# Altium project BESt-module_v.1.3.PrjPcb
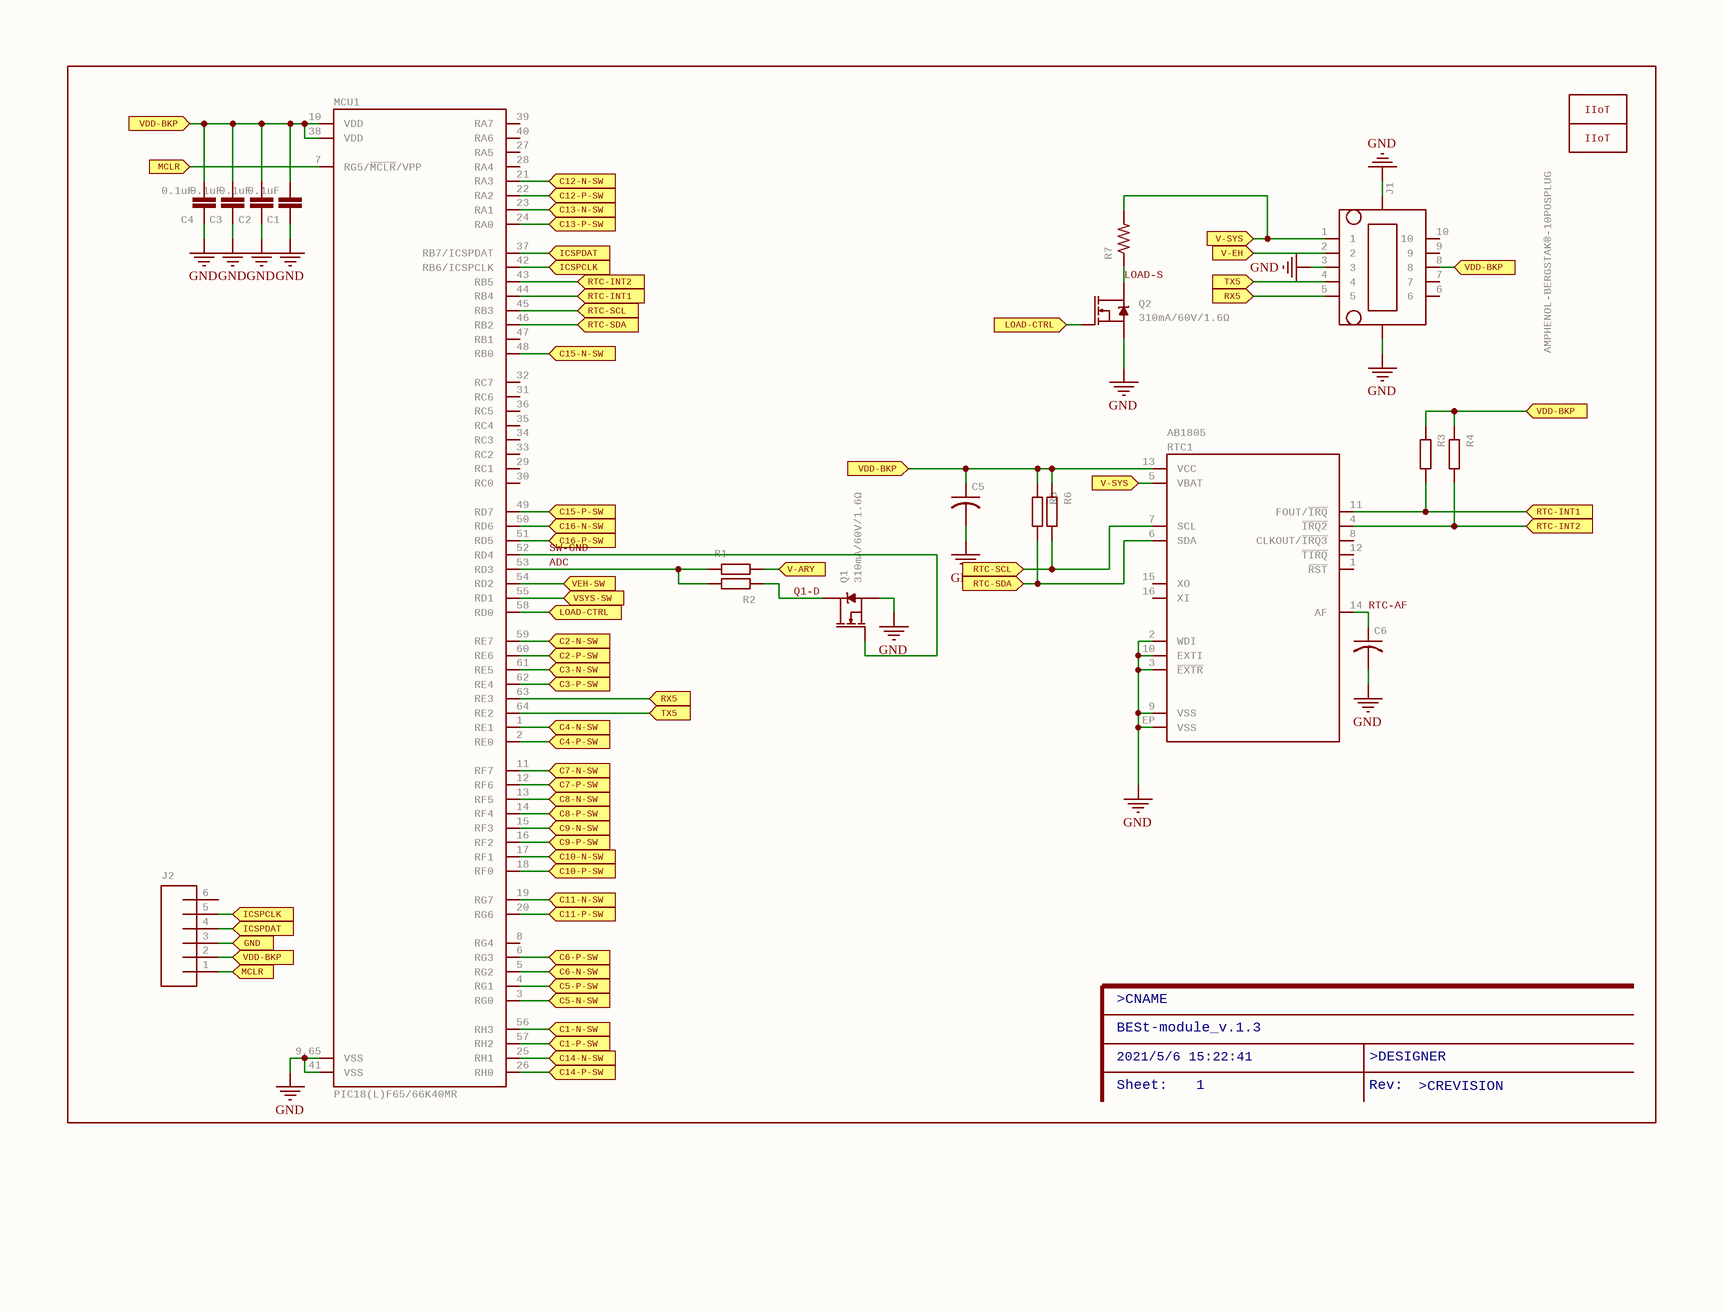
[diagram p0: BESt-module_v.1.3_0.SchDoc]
2 sheets, 61 parts. Net scope: flat (ports and power ports of the same name join across sheets).
Board file: BESt-module_v.1.3.PcbDoc
Sheets:
  BESt-module_v.1.3_0.SchDoc
  BESt-module_v.1.3_1.SchDoc

## Sheet BESt-module_v.1.3_0.SchDoc: BESt-module_v.1.3
size 302 x 229 mm; Origin: Eagle; Date: 2021/5/6 15:22:41; SheetNumber: 1; GateName_1: G$1; SymbolName_1: FR-A4L; LibraryName: SparkFun-Aesthetics; DeviceSetName: FRAME-A4L; Sheet: Sheet:; CNAME: >CNAME; Rev: Rev:; DESIGNER: >DESIGNER; CREVISION: >CREVISION

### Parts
C1  0.1uF  [0603]
C2  0.1uF  [0603]
C3  0.1uF  [0603]
C4  0.1uF  [0603]
C5  C-USC0402  [C0402]  (value not drawn)
C6  C-USC0402  [C0402]  (value not drawn)
J1  AMPHENOL-BERGSTAK®-10POSPLUG  [10132797-10POS-PLUG]
J2  CONN_06NO_SILK_NO_POP  [1X06_NO_SILK]  (value not drawn)
LOGO1  IIOT  [IIOT]
LOGO2  IIOT  [IIOT]
MCU1  PIC18(L)F65/66K40MR  [QFN50P900X900X100-65T715N]
Q1  310mA/60V/1.6Ω  [SOT323]
Q2  310mA/60V/1.6Ω  [SOT323]
R1  R-EU_R0402  [R0402]  (value not drawn)
R2  R-EU_R0402  [R0402]  (value not drawn)
R3  R-EU_R0402  [R0402]  (value not drawn)
R4  R-EU_R0402  [R0402]  (value not drawn)
R5  R-EU_R0402  [R0402]  (value not drawn)
R6  R-EU_R0402  [R0402]  (value not drawn)
R7  R-US_R0805  [R0805]  (value not drawn)
RTC1  AB1805  [QFN-16-3X3]

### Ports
C1-N-SW (in), C1-P-SW (in), C2-N-SW (in), C2-P-SW (in), C3-N-SW (in), C3-P-SW (in), C4-N-SW (in), C4-P-SW (in), C5-N-SW (in), C5-P-SW (in), C6-N-SW (in), C6-P-SW (in), C7-N-SW (in), C7-P-SW (in), C8-N-SW (in), C8-P-SW (in), C9-N-SW (in), C9-P-SW (in), C10-N-SW (in), C10-P-SW (in), C11-N-SW (in), C11-P-SW (in), C12-N-SW (in), C12-P-SW (in), C13-N-SW (in), C13-P-SW (in), C14-N-SW (in), C14-P-SW (in), C15-N-SW (in), C15-P-SW (in), C16-N-SW (in), C16-P-SW (in), GND (in), ICSPCLK (in), ICSPDAT (in), LOAD-CTRL (in), MCLR (in), RTC-INT1 (in), RTC-INT2 (in), RTC-SCL (in), RTC-SDA (in), RX5 (in), TX5 (in), V-ARY (in), V-EH (in), V-SYS (in), VDD-BKP (in), VEH-SW (in), VSYS-SW (in)

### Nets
GND: C1.1 C2.1 C3.1 C4.1 C5.2 C6.2 J1.3 J1.MNT1 J1.MNT2 MCU1.9,65(VSS) MCU1.41(VSS) Q1.2(S) Q2.2(S) RTC1.2(WDI) RTC1.3(~{EXTR}) RTC1.9(VSS) RTC1.10(EXTI) RTC1.EP(VSS)
ADC: MCU1.53(RD3) R1.1 R2.2
C9-N: MCU1.16(RF2) ; port C9-P-SW
LOAD-S: Q2.3(D) R7.1
Q1-D: Q1.3(D) R2.1
RTC-AF: C6.1 RTC1.14(AF)
SW-GND: MCU1.52(RD4) Q1.1(G)
NetC1_2: C1.2 C2.2 C3.2 C4.2 C5.1 J1.8 J2.2 MCU1.10(VDD) MCU1.38(VDD) R3.1 R4.1 R5.1 R6.1 RTC1.13(VCC) ; port VDD-BKP
NetJ1_1: J1.1 R7.2 RTC1.5(VBAT) ; port V-SYS
NetJ1_2: J1.2 ; port V-EH
NetJ1_4: J1.4 MCU1.64(RE2) ; port TX5
NetJ1_5: J1.5 MCU1.63(RE3) ; port RX5
NetJ2_1: J2.1 MCU1.7(RG5/~{MCLR}/VPP) ; port MCLR
NetJ2_3: J2.3 ; port GND
NetJ2_4: J2.4 MCU1.37(RB7/ICSPDAT) ; port ICSPDAT
NetJ2_5: J2.5 MCU1.42(RB6/ICSPCLK) ; port ICSPCLK
NetMCU1_1: MCU1.1(RE1) ; port C4-N-SW
NetMCU1_2: MCU1.2(RE0) ; port C4-P-SW
NetMCU1_3: MCU1.3(RG0) ; port C5-N-SW
NetMCU1_4: MCU1.4(RG1) ; port C5-P-SW
NetMCU1_5: MCU1.5(RG2) ; port C6-N-SW
NetMCU1_6: MCU1.6(RG3) ; port C6-P-SW
NetMCU1_11: MCU1.11(RF7) ; port C7-N-SW
NetMCU1_12: MCU1.12(RF6) ; port C7-P-SW
NetMCU1_13: MCU1.13(RF5) ; port C8-N-SW
NetMCU1_14: MCU1.14(RF4) ; port C8-P-SW
NetMCU1_15: MCU1.15(RF3) ; port C9-N-SW
NetMCU1_17: MCU1.17(RF1) ; port C10-N-SW
NetMCU1_18: MCU1.18(RF0) ; port C10-P-SW
NetMCU1_19: MCU1.19(RG7) ; port C11-N-SW
NetMCU1_20: MCU1.20(RG6) ; port C11-P-SW
NetMCU1_21: MCU1.21(RA3) ; port C12-N-SW
NetMCU1_22: MCU1.22(RA2) ; port C12-P-SW
NetMCU1_23: MCU1.23(RA1) ; port C13-N-SW
NetMCU1_24: MCU1.24(RA0) ; port C13-P-SW
NetMCU1_25: MCU1.25(RH1) ; port C14-N-SW
NetMCU1_26: MCU1.26(RH0) ; port C14-P-SW
NetMCU1_43: MCU1.43(RB5) R4.2 RTC1.4(~{IRQ2}) ; port RTC-INT2
NetMCU1_44: MCU1.44(RB4) R3.2 RTC1.11(FOUT/~{IRQ}) ; port RTC-INT1
NetMCU1_45: MCU1.45(RB3) R6.2 RTC1.7(SCL) ; port RTC-SCL
NetMCU1_46: MCU1.46(RB2) R5.2 RTC1.6(SDA) ; port RTC-SDA
NetMCU1_48: MCU1.48(RB0) ; port C15-N-SW
NetMCU1_49: MCU1.49(RD7) ; port C15-P-SW
NetMCU1_50: MCU1.50(RD6) ; port C16-N-SW
NetMCU1_51: MCU1.51(RD5) ; port C16-P-SW
NetMCU1_54: MCU1.54(RD2) ; port VEH-SW
NetMCU1_55: MCU1.55(RD1) ; port VSYS-SW
NetMCU1_56: MCU1.56(RH3) ; port C1-N-SW
NetMCU1_57: MCU1.57(RH2) ; port C1-P-SW
NetMCU1_58: MCU1.58(RD0) Q2.1(G) ; port LOAD-CTRL
NetMCU1_59: MCU1.59(RE7) ; port C2-N-SW
NetMCU1_60: MCU1.60(RE6) ; port C2-P-SW
NetMCU1_61: MCU1.61(RE5) ; port C3-N-SW
NetMCU1_62: MCU1.62(RE4) ; port C3-P-SW
NetR1_2: R1.2 ; port V-ARY

Not connected (* = marked no-connect by the designer): J1 6 7 9 10; J2 6; MCU1 8(RG4) 27(RA5) 28(RA4) 29(RC1) 30(RC0) 31(RC6) 32(RC7) 33(RC2) 34(RC3) 35(RC4) 36(RC5) 39(RA7) 40(RA6) 47(RB1); RTC1 1(~{RST}) 8(CLKOUT/~{IRQ3}) 12(~{TIRQ}) 15(XO) 16(XI)

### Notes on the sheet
- BESt-module_v.1.3
- >CNAME
- 2021/5/6 15:22:41
- Sheet:
- 1
- Rev:
- >DESIGNER
- >CREVISION

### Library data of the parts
C1-C4 = 0.1UF-0603-25V-5%: 0.1碌F ceramic capacitors    A capacitor is a passive two-terminal electrical component used to store electrical energy temporarily in an electric field.; GateName_1: G$1; SymbolName_1: CAP; PROD_ID: CAP-08604
C5 C6 = C-USC0402: CAPACITOR, American symbol; GateName_1: G$1; SymbolName_1: C-US
J1 = AMPHENOL-BERGSTAK®-10POSPLUG: Amphenol鈥檚 BergStak庐 0.5mm is a comprehensive and versatile board-to-board solution designed for reliable and high-density applications. The unique design of scoop-proof housing ensures terminals are not damaged during mating.; GateName_1: G$1; SymbolName_1: 2X5WAY-B2B; DeviceName: PLUG
J2 = CONN_06NO_SILK_NO_POP: Multi connection point. Often used as Generic Header-pin footprint for 0.1 inch spaced/style header connections    On any of the 0.1 inch spaced packages, you can populate with these:  Break Away Headers - Straight (PRT-00116)   Break Away Male Headers - Right Angle (PRT-00553)   Female Headers (PRT-00115)   Break Away Headers - Machine Pin (PRT-00117)   Break Away Female Headers - Swiss Machine Pin (PRT-00743)   Arduino Stackable Header - 6 Pin (PRT-09280)        For SCREWTERMINALS and SPRING TERMINALS visit here:  Screw Terimnals on SparkFun.com (5mm/3.5mm/2.54mm spacing)       This device is also useful as a general connection point to wire up your design to another part of your project. Our various solder wires solder well into these plated through hole pads.  Hook-Up Wire - Assortment (Stranded, 22 AWG) (PRT-11375)   Hook-Up Wire - Assortment (Solid Core, 22 AWG) (PRT-11367)   View the entire wire category on our website here; GateName_1: G$1
LOGO1 LOGO2 = IIOT: GateName_1: G$1
MCU1 = PIC18(L)F65/66K40MR: 64-Pin, Low-Power, High-Performance Microcontrollers with XLP Technology; GateName_1: G$1; DeviceName: MR
Q1 Q2 = MOSFET-NCH-2N7002PW: N-channel MOSFETs    Voltage controlled devices that allow control of high current outputs.   SparkFun Products:; GateName_1: NMOS; SymbolName_1: LABELED-NMOS; PROD_ID: TRANS-11151
R1-R6 = R-EU_R0402: RESISTOR, European symbol; GateName_1: G$1; SymbolName_1: R-EU; DeviceSetName: R-EU_; POPULARITY: 0
R7 = R-US_R0805: RESISTOR, American symbol; GateName_1: G$1; SymbolName_1: R-US; DeviceSetName: R-US_; POPULARITY: 85
RTC1 = AB1805: GateName_1: G$1

## Sheet BESt-module_v.1.3_1.SchDoc: BESt-module_v.1.3
size 302 x 228 mm; Origin: Eagle; Date: 2021/5/6 15:22:41; SheetNumber: 2; GateName_1: G$1; SymbolName_1: FR-A4L; LibraryName: SparkFun-Aesthetics; DeviceSetName: FRAME-A4L; Sheet: Sheet:; CNAME: >CNAME; Rev: Rev:; DESIGNER: >DESIGNER; CREVISION: >CREVISION
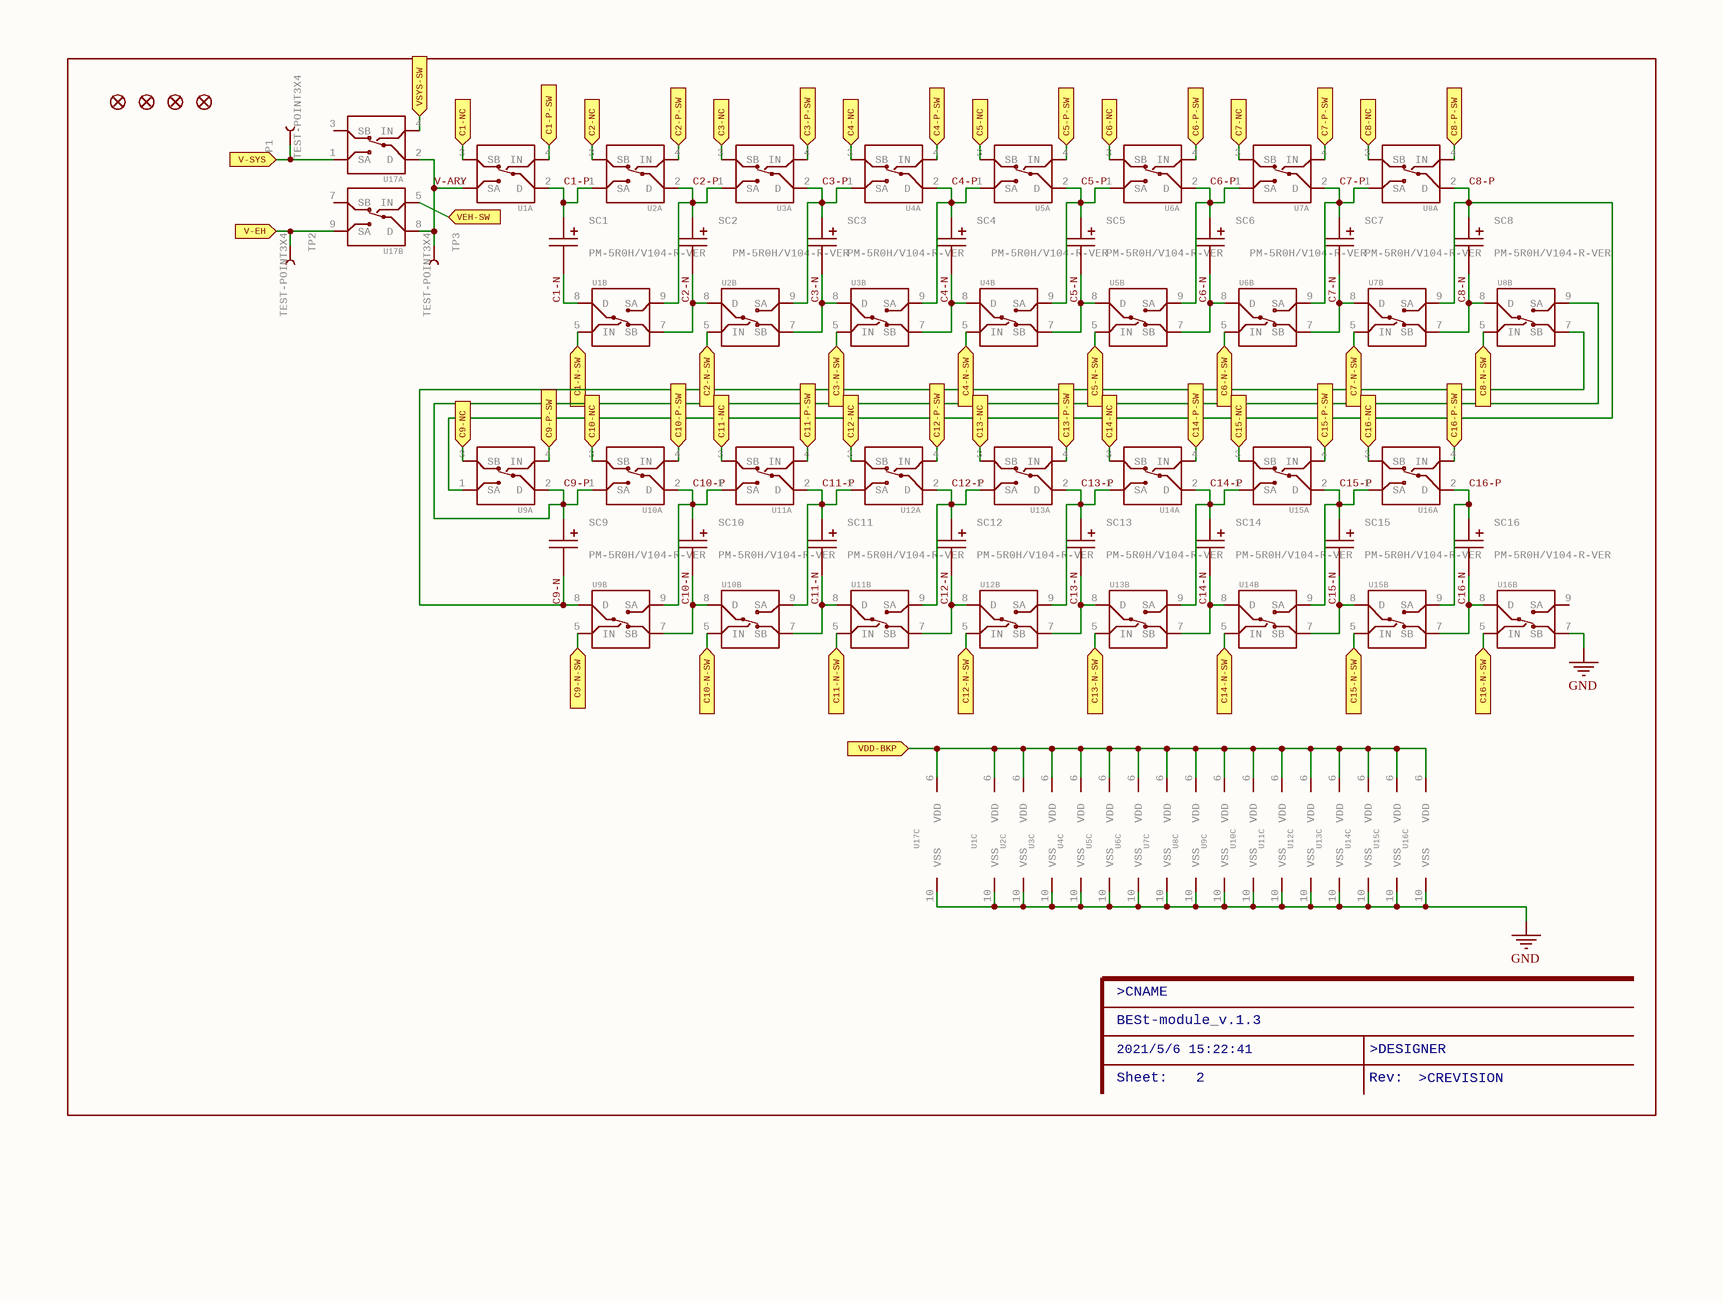
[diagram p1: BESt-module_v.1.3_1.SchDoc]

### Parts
FD1  FIDUCIAL1X2  [FIDUCIAL-1X2]  (value not drawn)
FD2  FIDUCIAL1X2  [FIDUCIAL-1X2]  (value not drawn)
FD3  FIDUCIAL1X2  [FIDUCIAL-1X2]  (value not drawn)
FD4  FIDUCIAL1X2  [FIDUCIAL-1X2]  (value not drawn)
SC1  PM-5R0H/V104-R-VER  [EATON-13X11.3X6-V]
SC2  PM-5R0H/V104-R-VER  [EATON-13X11.3X6-V]
SC3  PM-5R0H/V104-R-VER  [EATON-13X11.3X6-V]
SC4  PM-5R0H/V104-R-VER  [EATON-13X11.3X6-V]
SC5  PM-5R0H/V104-R-VER  [EATON-13X11.3X6-V]
SC6  PM-5R0H/V104-R-VER  [EATON-13X11.3X6-V]
SC7  PM-5R0H/V104-R-VER  [EATON-13X11.3X6-V]
SC8  PM-5R0H/V104-R-VER  [EATON-13X11.3X6-V]
SC9  PM-5R0H/V104-R-VER  [EATON-13X11.3X6-V]
SC10  PM-5R0H/V104-R-VER  [EATON-13X11.3X6-V]
SC11  PM-5R0H/V104-R-VER  [EATON-13X11.3X6-V]
SC12  PM-5R0H/V104-R-VER  [EATON-13X11.3X6-V]
SC13  PM-5R0H/V104-R-VER  [EATON-13X11.3X6-V]
SC14  PM-5R0H/V104-R-VER  [EATON-13X11.3X6-V]
SC15  PM-5R0H/V104-R-VER  [EATON-13X11.3X6-V]
SC16  PM-5R0H/V104-R-VER  [EATON-13X11.3X6-V]
TP1  TEST-POINT3X4  [PAD.03X.04]
TP2  TEST-POINT3X4  [PAD.03X.04]
TP3  TEST-POINT3X4  [PAD.03X.04]
U1  ADG824  [CP-10-10]  (value not drawn)  (parts A,B,C of 3)
U2  ADG824  [CP-10-10]  (value not drawn)  (parts A,B,C of 3)
U3  ADG824  [CP-10-10]  (value not drawn)  (parts A,B,C of 3)
U4  ADG824  [CP-10-10]  (value not drawn)  (parts A,B,C of 3)
U5  ADG824  [CP-10-10]  (value not drawn)  (parts A,B,C of 3)
U6  ADG824  [CP-10-10]  (value not drawn)  (parts A,B,C of 3)
U7  ADG824  [CP-10-10]  (value not drawn)  (parts A,B,C of 3)
U8  ADG824  [CP-10-10]  (value not drawn)  (parts A,B,C of 3)
U9  ADG824  [CP-10-10]  (value not drawn)  (parts A,B,C of 3)
U10  ADG824  [CP-10-10]  (value not drawn)  (parts A,B,C of 3)
U11  ADG824  [CP-10-10]  (value not drawn)  (parts A,B,C of 3)
U12  ADG824  [CP-10-10]  (value not drawn)  (parts A,B,C of 3)
U13  ADG824  [CP-10-10]  (value not drawn)  (parts A,B,C of 3)
U14  ADG824  [CP-10-10]  (value not drawn)  (parts A,B,C of 3)
U15  ADG824  [CP-10-10]  (value not drawn)  (parts A,B,C of 3)
U16  ADG824  [CP-10-10]  (value not drawn)  (parts A,B,C of 3)
U17  ADG824  [CP-10-10]  (value not drawn)  (parts A,B,C of 3)

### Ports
C1-N-SW (in), C1-NC (in), C1-P-SW (in), C2-N-SW (in), C2-NC (in), C2-P-SW (in), C3-N-SW (in), C3-NC (in), C3-P-SW (in), C4-N-SW (in), C4-NC (in), C4-P-SW (in), C5-N-SW (in), C5-NC (in), C5-P-SW (in), C6-N-SW (in), C6-NC (in), C6-P-SW (in), C7-N-SW (in), C7-NC (in), C7-P-SW (in), C8-N-SW (in), C8-NC (in), C8-P-SW (in), C9-N-SW (in), C9-NC (in), C9-P-SW (in), C10-N-SW (in), C10-NC (in), C10-P-SW (in), C11-N-SW (in), C11-NC (in), C11-P-SW (in), C12-N-SW (in), C12-NC (in), C12-P-SW (in), C13-N-SW (in), C13-NC (in), C13-P-SW (in), C14-N-SW (in), C14-NC (in), C14-P-SW (in), C15-N-SW (in), C15-NC (in), C15-P-SW (in), C16-N-SW (in), C16-NC (in), C16-P-SW (in), V-EH (in), V-SYS (in), VDD-BKP (in), VEH-SW (in), VSYS-SW (in)

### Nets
GND: U1.10(VSS) U2.10(VSS) U3.10(VSS) U4.10(VSS) U5.10(VSS) U6.10(VSS) U7.10(VSS) U8.10(VSS) U9.10(VSS) U10.10(VSS) U11.10(VSS) U12.10(VSS) U13.10(VSS) U14.10(VSS) U15.10(VSS) U16.7(SB) U16.10(VSS) U17.10(VSS)
C1-N: SC1.N U1.8(D)
C1-P: SC1.P U1.2(D) U2.1(SA)
C2-N: SC2.N U1.7(SB) U2.8(D)
C2-P: SC2.P U1.9(SA) U2.2(D) U3.1(SA)
C3-N: SC3.N U2.7(SB) U3.8(D)
C3-P: SC3.P U2.9(SA) U3.2(D) U4.1(SA)
C4-N: SC4.N U3.7(SB) U4.8(D)
C4-P: SC4.P U3.9(SA) U4.2(D) U5.1(SA)
C5-N: SC5.N U4.7(SB) U5.8(D)
C5-P: SC5.P U4.9(SA) U5.2(D) U6.1(SA)
C6-N: SC6.N U5.7(SB) U6.8(D)
C6-P: SC6.P U5.9(SA) U6.2(D) U7.1(SA)
C7-N: SC7.N U6.7(SB) U7.8(D)
C7-P: SC7.P U6.9(SA) U7.2(D) U8.1(SA)
C8-N: SC8.N U7.7(SB) U8.8(D)
C8-P: SC8.P U7.9(SA) U8.2(D) U9.1(SA)
C9-N: SC9.N U8.7(SB) U9.4(IN) U9.8(D) ; port C9-P-SW
C9-P: SC9.P U8.9(SA) U9.2(D) U10.1(SA)
C10-N: SC10.N U9.7(SB) U10.8(D)
C10-P: SC10.P U9.9(SA) U10.2(D) U11.1(SA)
C11-N: SC11.N U10.7(SB) U11.8(D)
C11-P: SC11.P U10.9(SA) U11.2(D) U12.1(SA)
C12-N: SC12.N U11.7(SB) U12.8(D)
C12-P: SC12.P U11.9(SA) U12.2(D) U13.1(SA)
C13-N: SC13.N U12.7(SB) U13.8(D)
C13-P: SC13.P U12.9(SA) U13.2(D) U14.1(SA)
C14-N: SC14.N U13.7(SB) U14.8(D)
C14-P: SC14.P U13.9(SA) U14.2(D) U15.1(SA)
C15-N: SC15.N U14.7(SB) U15.8(D)
C15-P: SC15.P U14.9(SA) U15.2(D) U16.1(SA)
C16-N: SC16.N U15.7(SB) U16.8(D)
C16-P: SC16.P U15.9(SA) U16.2(D)
V-ARY: TP3.P$1 U1.1(SA) U17.2(D) U17.8(D)
NetC1_2: U1.6(VDD) U2.6(VDD) U3.6(VDD) U4.6(VDD) U5.6(VDD) U6.6(VDD) U7.6(VDD) U8.6(VDD) U9.6(VDD) U10.6(VDD) U11.6(VDD) U12.6(VDD) U13.6(VDD) U14.6(VDD) U15.6(VDD) U16.6(VDD) U17.6(VDD) ; port VDD-BKP
NetJ1_1: TP1.P$1 U17.1(SA) ; port V-SYS
NetJ1_2: TP2.P$1 U17.9(SA) ; port V-EH
NetMCU1_1: U4.5(IN) ; port C4-N-SW
NetMCU1_2: U4.4(IN) ; port C4-P-SW
NetMCU1_3: U5.5(IN) ; port C5-N-SW
NetMCU1_4: U5.4(IN) ; port C5-P-SW
NetMCU1_5: U6.5(IN) ; port C6-N-SW
NetMCU1_6: U6.4(IN) ; port C6-P-SW
NetMCU1_11: U7.5(IN) ; port C7-N-SW
NetMCU1_12: U7.4(IN) ; port C7-P-SW
NetMCU1_13: U8.5(IN) ; port C8-N-SW
NetMCU1_14: U8.4(IN) ; port C8-P-SW
NetMCU1_15: U9.5(IN) ; port C9-N-SW
NetMCU1_17: U10.5(IN) ; port C10-N-SW
NetMCU1_18: U10.4(IN) ; port C10-P-SW
NetMCU1_19: U11.5(IN) ; port C11-N-SW
NetMCU1_20: U11.4(IN) ; port C11-P-SW
NetMCU1_21: U12.5(IN) ; port C12-N-SW
NetMCU1_22: U12.4(IN) ; port C12-P-SW
NetMCU1_23: U13.5(IN) ; port C13-N-SW
NetMCU1_24: U13.4(IN) ; port C13-P-SW
NetMCU1_25: U14.5(IN) ; port C14-N-SW
NetMCU1_26: U14.4(IN) ; port C14-P-SW
NetMCU1_48: U15.5(IN) ; port C15-N-SW
NetMCU1_49: U15.4(IN) ; port C15-P-SW
NetMCU1_50: U16.5(IN) ; port C16-N-SW
NetMCU1_51: U16.4(IN) ; port C16-P-SW
NetMCU1_54: U17.5(IN) ; port VEH-SW
NetMCU1_55: U17.4(IN) ; port VSYS-SW
NetMCU1_56: U1.5(IN) ; port C1-N-SW
NetMCU1_57: U1.4(IN) ; port C1-P-SW
NetMCU1_59: U2.5(IN) ; port C2-N-SW
NetMCU1_60: U2.4(IN) ; port C2-P-SW
NetMCU1_61: U3.5(IN) ; port C3-N-SW
NetMCU1_62: U3.4(IN) ; port C3-P-SW
NetU1_3: U1.3(SB) ; port C1-NC
NetU2_3: U2.3(SB) ; port C2-NC
NetU3_3: U3.3(SB) ; port C3-NC
NetU4_3: U4.3(SB) ; port C4-NC
NetU5_3: U5.3(SB) ; port C5-NC
NetU6_3: U6.3(SB) ; port C6-NC
NetU7_3: U7.3(SB) ; port C7-NC
NetU8_3: U8.3(SB) ; port C8-NC
NetU9_3: U9.3(SB) ; port C9-NC
NetU10_3: U10.3(SB) ; port C10-NC
NetU11_3: U11.3(SB) ; port C11-NC
NetU12_3: U12.3(SB) ; port C12-NC
NetU13_3: U13.3(SB) ; port C13-NC
NetU14_3: U14.3(SB) ; port C14-NC
NetU15_3: U15.3(SB) ; port C15-NC
NetU16_3: U16.3(SB) ; port C16-NC

Not connected (* = marked no-connect by the designer): U16 9(SA); U17 3(SB) 7(SB)

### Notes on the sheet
- BESt-module_v.1.3
- >CNAME
- 2021/5/6 15:22:41
- Sheet:
- 2
- Rev:
- >DESIGNER
- >CREVISION

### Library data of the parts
FD1-FD4 = FIDUCIAL1X2: Fiducial Alignment Points    Point-of-reference for pick-and-place machines and other optical instruments.; GateName_1: G$1; DeviceName: 1X2
SC1-SC16 = PM-5R0H/V104-R-VER: CAP 100MF -20% +80% 5V T/H; GateName_1: G$1; SymbolName_1: C; DeviceName: -VER
TP1-TP3 = TEST-POINT3X4: SparkFun Test Points    Bare copper test points for troubleshooting or In-Circuit-Testing. These are used by our Production team for verifying production board runs using pogo-pins on test beds.   SparkFun Products:     SparkFun Load Cell Amplifier; GateName_1: G$1; DeviceName: 3X4
U1-U17 = ADG824: 0.5 鈩?CMOS 1.65 V to 3.6 V Dual SPDT/2:1 Mux in Mini LFCSP Package; GateName_1: P1; SymbolName_1: MUX(2:1); GateName_2: P2; GateName_3: PWR

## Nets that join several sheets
GND: BESt-module_v.1.3_0 (18 pins), BESt-module_v.1.3_1 (18 pins)
C9-N: BESt-module_v.1.3_0 (MCU1.16), BESt-module_v.1.3_1 (SC9.N U8.7 U9.4 U9.8)
NetC1_2: BESt-module_v.1.3_0 (14 pins), BESt-module_v.1.3_1 (17 pins)
NetJ1_1: BESt-module_v.1.3_0 (J1.1 R7.2 RTC1.5), BESt-module_v.1.3_1 (TP1.P$1 U17.1)
NetJ1_2: BESt-module_v.1.3_0 (J1.2), BESt-module_v.1.3_1 (TP2.P$1 U17.9)
NetMCU1_1: BESt-module_v.1.3_0 (MCU1.1), BESt-module_v.1.3_1 (U4.5)
NetMCU1_2: BESt-module_v.1.3_0 (MCU1.2), BESt-module_v.1.3_1 (U4.4)
NetMCU1_3: BESt-module_v.1.3_0 (MCU1.3), BESt-module_v.1.3_1 (U5.5)
NetMCU1_4: BESt-module_v.1.3_0 (MCU1.4), BESt-module_v.1.3_1 (U5.4)
NetMCU1_5: BESt-module_v.1.3_0 (MCU1.5), BESt-module_v.1.3_1 (U6.5)
NetMCU1_6: BESt-module_v.1.3_0 (MCU1.6), BESt-module_v.1.3_1 (U6.4)
NetMCU1_11: BESt-module_v.1.3_0 (MCU1.11), BESt-module_v.1.3_1 (U7.5)
NetMCU1_12: BESt-module_v.1.3_0 (MCU1.12), BESt-module_v.1.3_1 (U7.4)
NetMCU1_13: BESt-module_v.1.3_0 (MCU1.13), BESt-module_v.1.3_1 (U8.5)
NetMCU1_14: BESt-module_v.1.3_0 (MCU1.14), BESt-module_v.1.3_1 (U8.4)
NetMCU1_15: BESt-module_v.1.3_0 (MCU1.15), BESt-module_v.1.3_1 (U9.5)
NetMCU1_17: BESt-module_v.1.3_0 (MCU1.17), BESt-module_v.1.3_1 (U10.5)
NetMCU1_18: BESt-module_v.1.3_0 (MCU1.18), BESt-module_v.1.3_1 (U10.4)
NetMCU1_19: BESt-module_v.1.3_0 (MCU1.19), BESt-module_v.1.3_1 (U11.5)
NetMCU1_20: BESt-module_v.1.3_0 (MCU1.20), BESt-module_v.1.3_1 (U11.4)
NetMCU1_21: BESt-module_v.1.3_0 (MCU1.21), BESt-module_v.1.3_1 (U12.5)
NetMCU1_22: BESt-module_v.1.3_0 (MCU1.22), BESt-module_v.1.3_1 (U12.4)
NetMCU1_23: BESt-module_v.1.3_0 (MCU1.23), BESt-module_v.1.3_1 (U13.5)
NetMCU1_24: BESt-module_v.1.3_0 (MCU1.24), BESt-module_v.1.3_1 (U13.4)
NetMCU1_25: BESt-module_v.1.3_0 (MCU1.25), BESt-module_v.1.3_1 (U14.5)
NetMCU1_26: BESt-module_v.1.3_0 (MCU1.26), BESt-module_v.1.3_1 (U14.4)
NetMCU1_48: BESt-module_v.1.3_0 (MCU1.48), BESt-module_v.1.3_1 (U15.5)
NetMCU1_49: BESt-module_v.1.3_0 (MCU1.49), BESt-module_v.1.3_1 (U15.4)
NetMCU1_50: BESt-module_v.1.3_0 (MCU1.50), BESt-module_v.1.3_1 (U16.5)
NetMCU1_51: BESt-module_v.1.3_0 (MCU1.51), BESt-module_v.1.3_1 (U16.4)
NetMCU1_54: BESt-module_v.1.3_0 (MCU1.54), BESt-module_v.1.3_1 (U17.5)
NetMCU1_55: BESt-module_v.1.3_0 (MCU1.55), BESt-module_v.1.3_1 (U17.4)
NetMCU1_56: BESt-module_v.1.3_0 (MCU1.56), BESt-module_v.1.3_1 (U1.5)
NetMCU1_57: BESt-module_v.1.3_0 (MCU1.57), BESt-module_v.1.3_1 (U1.4)
NetMCU1_59: BESt-module_v.1.3_0 (MCU1.59), BESt-module_v.1.3_1 (U2.5)
NetMCU1_60: BESt-module_v.1.3_0 (MCU1.60), BESt-module_v.1.3_1 (U2.4)
NetMCU1_61: BESt-module_v.1.3_0 (MCU1.61), BESt-module_v.1.3_1 (U3.5)
NetMCU1_62: BESt-module_v.1.3_0 (MCU1.62), BESt-module_v.1.3_1 (U3.4)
